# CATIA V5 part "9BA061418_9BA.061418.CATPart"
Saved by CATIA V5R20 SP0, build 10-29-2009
Part number: 9BA061418_9BA.061418
Revision: ANY
Definition: UNKNOWN
Nomenclature: 9BA061418_9BA.061418
Source: Unknown
Bounding box of the stored display mesh (mm): x -9 to 9, y 0 to 25.5, z -9 to 9
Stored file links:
  C:\Users\Utente\Desktop\IO LAVORO\3D X SITO CF\CUMSA\3D files BA\BA 061418\9BA061418_9BA.061418.CATPart
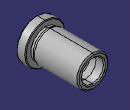
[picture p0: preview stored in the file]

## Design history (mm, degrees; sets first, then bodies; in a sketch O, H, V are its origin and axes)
Body1 "Cortar-Extruir1" (main body)
  Solid1: solid without history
